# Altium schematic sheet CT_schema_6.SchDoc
size 368 x 245 mm
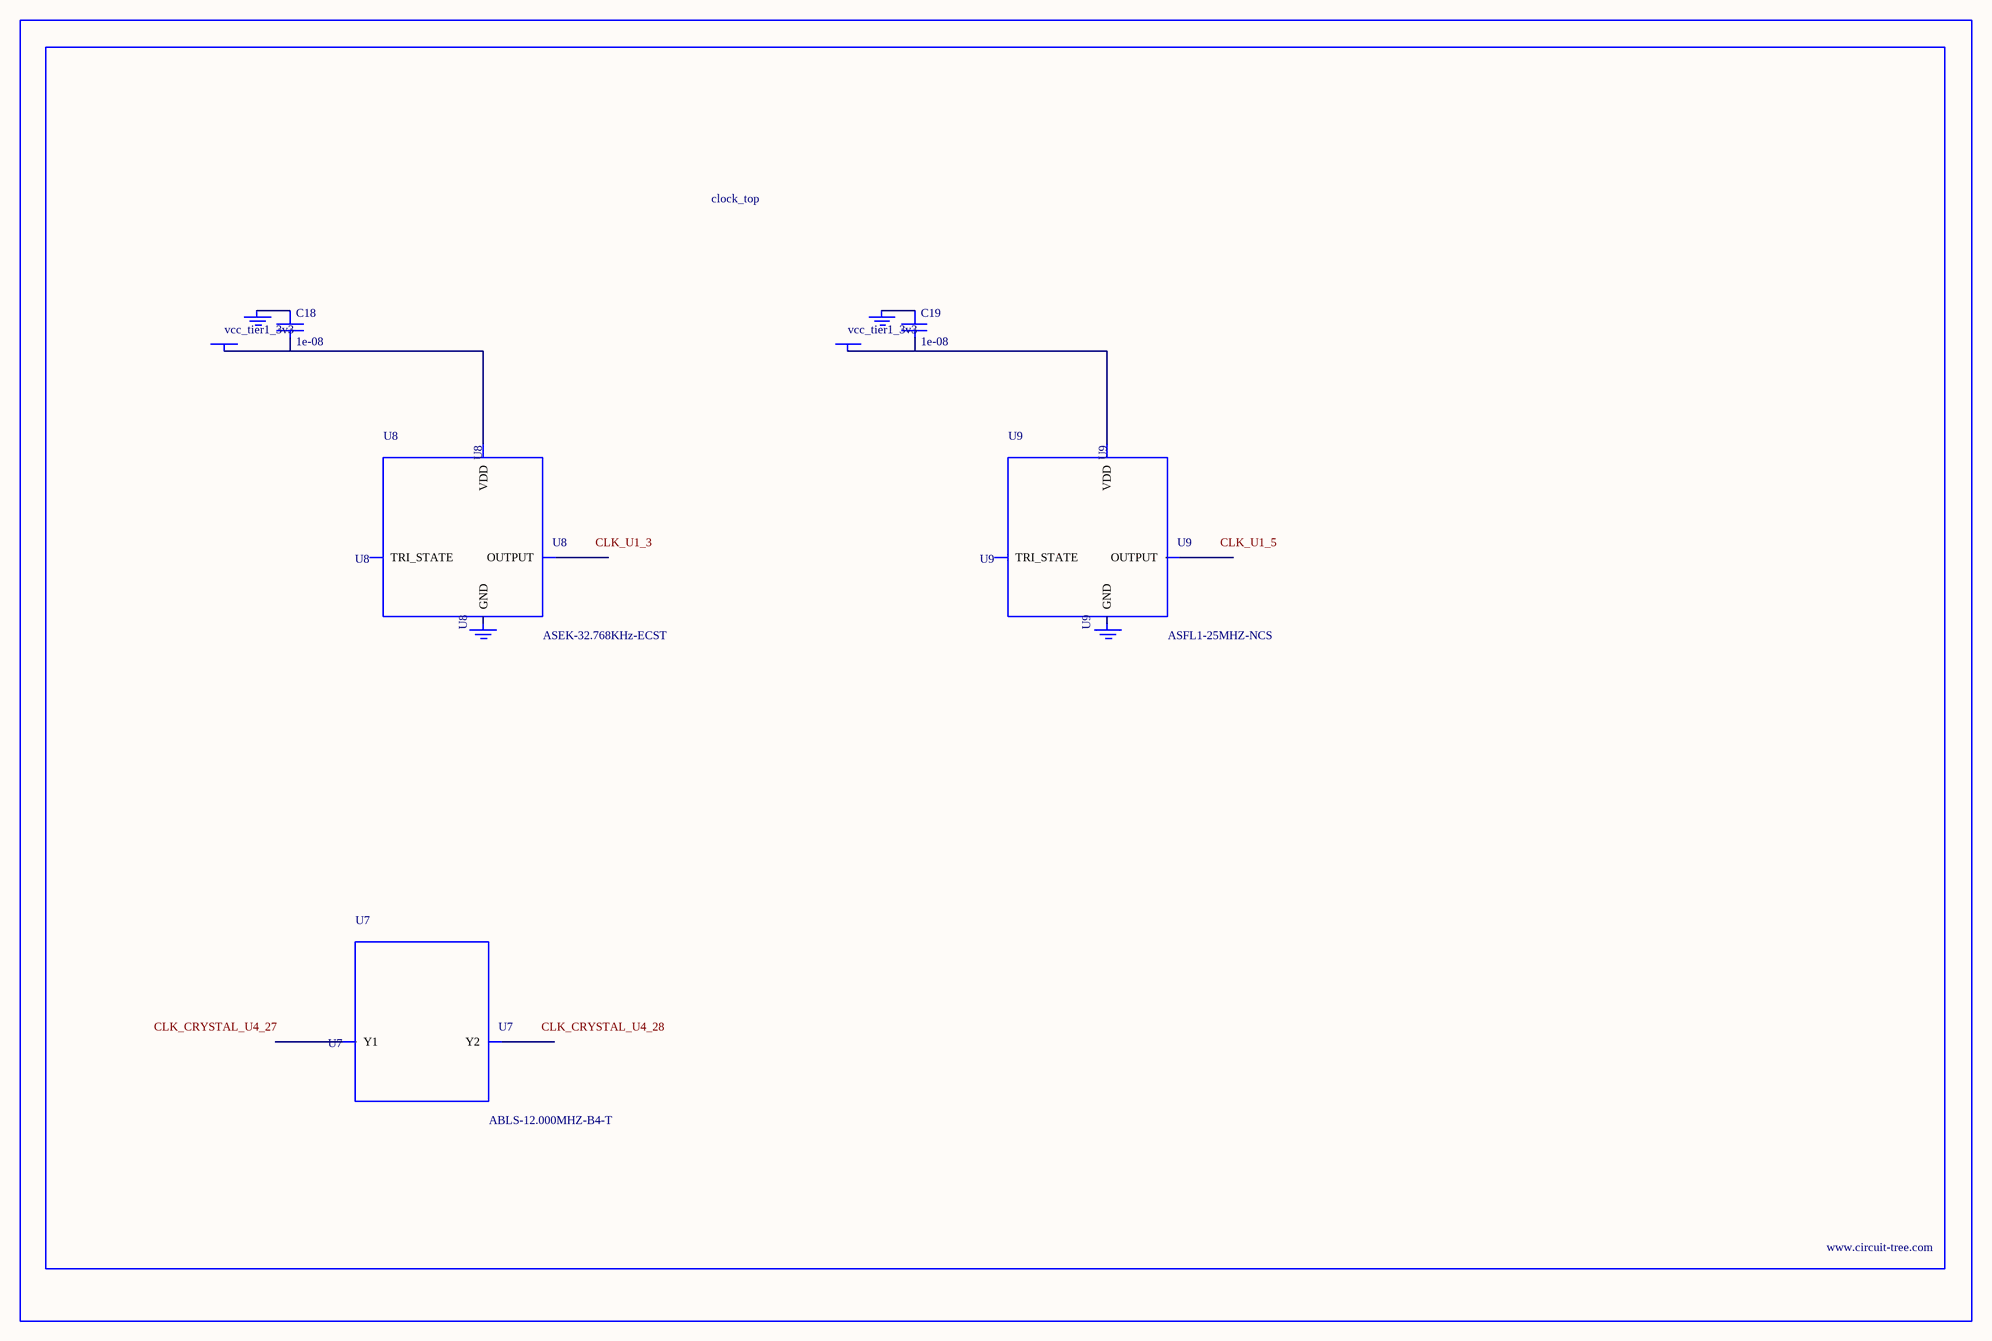
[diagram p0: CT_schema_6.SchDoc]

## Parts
BORDER5  (no value)
C18  1e-08  [C0402]
C19  1e-08  [C0402]
GND_INSTANCE_5_0  (no value)
GND_INSTANCE_5_1  (no value)
GND_INSTANCE_5_2  (no value)
GND_INSTANCE_5_3  (no value)
POWER_INSTANCE_5_0  vcc_tier1_3v3
POWER_INSTANCE_5_1  vcc_tier1_3v3
U7  ABLS-12.000MHZ-B4-T  [ABLS-12.000MHZ-B4-T]
U8  ASEK-32.768KHz-ECST  [ASEK]
U9  ASFL1-25MHZ-NCS  [ASFL1]

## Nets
NetC18_1: C18.1 GND_INSTANCE_5_0.0(GND)
NetC18_2: C18.2 POWER_INSTANCE_5_0.0(PWR) U8.4(VDD)
NetC19_1: C19.1 GND_INSTANCE_5_2.0(GND)
NetC19_2: C19.2 POWER_INSTANCE_5_1.0(PWR) U9.4(VDD)

Not connected (* = marked no-connect by the designer): GND_INSTANCE_5_1 0(GND); GND_INSTANCE_5_3 0(GND); U7 1(Y1) 2(Y2); U8 1(TRI_STATE) 2(GND) 3(OUTPUT); U9 1(TRI_STATE) 2(GND) 3(OUTPUT)

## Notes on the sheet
- Labels drawn without touching a wire or pin: CLK_CRYSTAL_U4_27, CLK_CRYSTAL_U4_28, CLK_U1_3, CLK_U1_5

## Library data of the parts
BORDER5 = BORDER_PAGE5
C18 C19 = C0402C103K3RAC
GND_INSTANCE_5_0-GND_INSTANCE_5_3 = GND
POWER_INSTANCE_5_0 POWER_INSTANCE_5_1 = PWR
